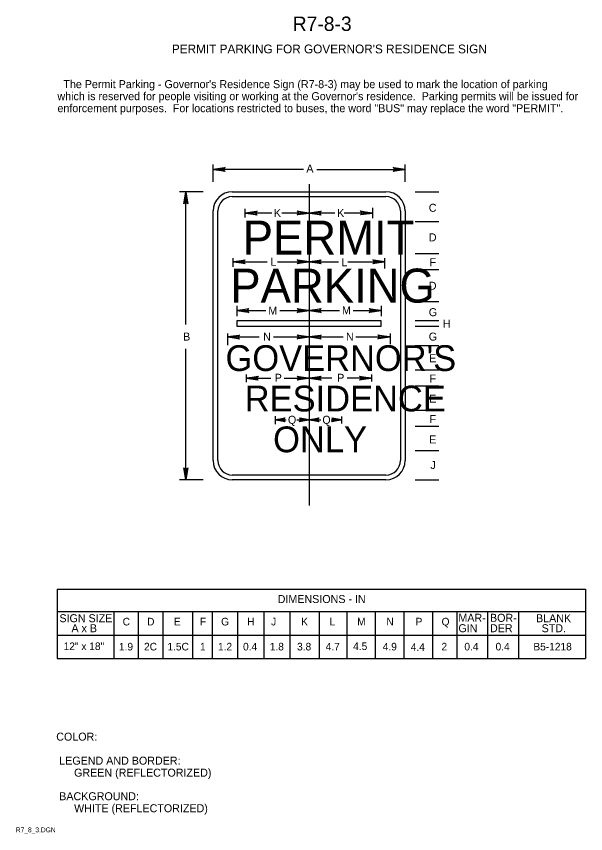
# Model space of a CAD drawing. Extents: x 0.013 to 0.191, y 0.004 to 0.259.
import ezdxf

# ---------------------------------------------------------------- set-up
doc = ezdxf.new("R2010")
doc.units = 0
for name, color, linetype in [('1', 7, 'Continuous'), ('11', 7, 'Continuous'), ('12', 7, 'Continuous'), ('3', 7, 'Continuous')]:
    doc.layers.add(name, color=color, linetype=linetype)

# ---------------------------------------------------------------- blocks, each defined once
blk = doc.blocks.new('RARROW')
at = {"layer": '3'}
for p, q in [((-2.156, 0.285), (-2.2665, 0.384625)), ((-2.2665, 0.384625), (0, 0)), ((0, 0), (-2.2665, -0.379125)), ((-2.156, 0.285), (-2.075625, 0.12075)), ((0, 0), (-2.156, 0.285)), ((-2.14975, -0.2705), (0, 0)), ((-2.075625, 0.12075), (0, 0)), ((0, 0), (-2.074, -0.108)), ((-2.2665, -0.379125), (-2.14975, -0.2705)), ((-2.074, -0.108), (-2.14975, -0.2705))]:
    blk.add_line(p, q, dxfattribs=at)

msp = doc.modelspace()

# ---------------------------------------------------------------- linework, layer by layer
at = {"layer": '11'}
for points in [[(0.08013, 0.2045), (0.12812, 0.2045)], [(0.07412, 0.1205), (0.07412, 0.1985)], [(0.13412, 0.1985), (0.13412, 0.1205)], [(0.12812, 0.1145), (0.08013, 0.1145)]]:
    msp.add_lwpolyline(points, dxfattribs=at)
for centre, start, end in [((0.08013, 0.1985), 90, 180), ((0.12812, 0.1985), 0, 90), ((0.08013, 0.1205), 180, 270), ((0.12812, 0.1205), 270, 0)]:
    msp.add_arc(centre, 0.006, start, end, dxfattribs=at)
at = {"layer": '12'}
for p, q in [((0.08415, 0.19649), (0.08415, 0.19922)), ((0.12388, 0.19948), (0.12388, 0.19628)), ((0.08038, 0.18109), (0.08038, 0.18374)), ((0.12775, 0.18054), (0.12775, 0.18374)), ((0.08149, 0.1689), (0.08149, 0.16562)), ((0.12667, 0.1689), (0.12667, 0.16562)), ((0.07862, 0.16026), (0.07862, 0.15659)), ((0.12947, 0.16025), (0.12947, 0.15692)), ((0.0845, 0.1474), (0.0845, 0.14499)), ((0.12362, 0.1474), (0.12362, 0.14521)), ((0.09349, 0.13436), (0.09349, 0.13184)), ((0.11427, 0.13433), (0.11427, 0.13215))]:
    msp.add_line(p, q, dxfattribs=at)
msp.add_lwpolyline([(0.08154, 0.16248), (0.12667, 0.16248), (0.12667, 0.16418), (0.08154, 0.16418)], close=True, dxfattribs=at)
at = {"layer": '3'}
for p, q in [((0.07412, 0.20763), (0.07412, 0.213)), ((0.13412, 0.20763), (0.13412, 0.213)), ((0.10238, 0.2115), (0.07537, 0.2115)), ((0.1065, 0.2115), (0.13412, 0.2115)), ((0.10412, 0.20688), (0.10412, 0.1065)), ((0.071, 0.2045), (0.06363, 0.2045)), ((0.06563, 0.163), (0.06563, 0.2045)), ((0.13725, 0.2045), (0.14463, 0.2045)), ((0.0925, 0.19787), (0.08413, 0.19787)), ((0.10412, 0.19787), (0.09557, 0.19787)), ((0.11213, 0.19787), (0.10412, 0.19787)), ((0.10413, 0.19871), (0.10413, 0.1971)), ((0.12388, 0.19787), (0.11507, 0.19787)), ((0.13725, 0.19525), (0.14463, 0.19525)), ((0.13725, 0.18525), (0.14463, 0.18525)), ((0.08038, 0.18263), (0.091, 0.18263)), ((0.09422, 0.18263), (0.10412, 0.18263)), ((0.10412, 0.18263), (0.11325, 0.18263)), ((0.1162, 0.18263), (0.12775, 0.18263)), ((0.13725, 0.18025), (0.14463, 0.18025)), ((0.13725, 0.17025), (0.14463, 0.17025)), ((0.0815, 0.16737), (0.09062, 0.16737)), ((0.095, 0.16737), (0.10412, 0.16737)), ((0.10412, 0.16737), (0.11363, 0.16737)), ((0.10413, 0.16834), (0.10413, 0.16673)), ((0.11788, 0.16737), (0.12667, 0.16737)), ((0.13725, 0.16425), (0.14463, 0.16425)), ((0.13725, 0.1625), (0.14463, 0.1625)), ((0.07863, 0.15913), (0.0885, 0.15913)), ((0.09294, 0.15913), (0.10412, 0.15913)), ((0.10412, 0.15913), (0.11475, 0.15913)), ((0.11868, 0.15913), (0.12947, 0.15913)), ((0.13725, 0.1565), (0.14463, 0.1565)), ((0.06563, 0.1145), (0.06563, 0.15545)), ((0.13725, 0.14888), (0.14463, 0.14888)), ((0.0845, 0.14625), (0.09215, 0.14625)), ((0.09632, 0.14625), (0.10407, 0.14625)), ((0.1112, 0.14625), (0.10407, 0.14625)), ((0.12362, 0.14625), (0.11596, 0.14625)), ((0.13725, 0.14388), (0.14463, 0.14388)), ((0.13725, 0.13625), (0.14463, 0.13625)), ((0.0935, 0.13325), (0.097, 0.13325)), ((0.10025, 0.13325), (0.10412, 0.13325)), ((0.10412, 0.13325), (0.10775, 0.13325)), ((0.111, 0.13325), (0.11427, 0.13325)), ((0.13725, 0.13125), (0.14463, 0.13125)), ((0.13725, 0.12362), (0.14463, 0.12362)), ((0.071, 0.1145), (0.06363, 0.1145)), ((0.13725, 0.1145), (0.14463, 0.1145)), ((0.02538, 0.08038), (0.1905, 0.08038)), ((0.02538, 0.08038), (0.02538, 0.05863)), ((0.1905, 0.08038), (0.1905, 0.05863)), ((0.02538, 0.07337), (0.1905, 0.07337)), ((0.04316, 0.07337), (0.04316, 0.05863)), ((0.05074, 0.0735), (0.05074, 0.05863)), ((0.05843, 0.07337), (0.05843, 0.05863)), ((0.06771, 0.0735), (0.06771, 0.05863)), ((0.0738, 0.0735), (0.0738, 0.05863)), ((0.08178, 0.07337), (0.08178, 0.05863)), ((0.08995, 0.07337), (0.08995, 0.05863)), ((0.0981, 0.07337), (0.0981, 0.05863)), ((0.10722, 0.07337), (0.10722, 0.05863)), ((0.11587, 0.07337), (0.11587, 0.05863)), ((0.12479, 0.07337), (0.12479, 0.05863)), ((0.13372, 0.07337), (0.13372, 0.05863)), ((0.14266, 0.0735), (0.14266, 0.05863)), ((0.15025, 0.07337), (0.15025, 0.05863)), ((0.15988, 0.07337), (0.15988, 0.05863)), ((0.1695, 0.07337), (0.1695, 0.05863)), ((0.02538, 0.066), (0.1905, 0.066)), ((0.02538, 0.05863), (0.1905, 0.05863))]:
    msp.add_line(p, q, dxfattribs=at)
for points in [[(0.08013, 0.203), (0.12812, 0.203)], [(0.07562, 0.1205), (0.07562, 0.1985)], [(0.13262, 0.1985), (0.13262, 0.1205)], [(0.12812, 0.116), (0.08013, 0.116)]]:
    msp.add_lwpolyline(points, dxfattribs=at)
for centre, start, end in [((0.08013, 0.1985), 90, 180), ((0.12812, 0.1985), 0, 90), ((0.08013, 0.1205), 180, 270), ((0.12812, 0.1205), 270, 0)]:
    msp.add_arc(centre, 0.0045, start, end, dxfattribs=at)

# ---------------------------------------------------------------- block references
for p, xscale, yscale, rotation in [((0.07412, 0.2115), 0.0016545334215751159, 0.0016366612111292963, 180), ((0.06563, 0.2045), 0.0016545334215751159, 0.0016366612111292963, 90), ((0.08413, 0.19787), 0.0016545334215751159, 0.0016366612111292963, 180), ((0.10412, 0.19787), 0.0016545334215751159, 0.0016366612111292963, 180), ((0.08038, 0.18263), 0.0016545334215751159, 0.0016366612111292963, 180), ((0.10412, 0.18263), 0.0016545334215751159, 0.0016366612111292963, 180), ((0.0815, 0.16737), 0.0016545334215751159, 0.0016366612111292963, 180), ((0.10412, 0.16737), 0.0016545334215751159, 0.0016366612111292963, 180), ((0.07863, 0.15913), 0.0016545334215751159, 0.0016366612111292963, 180), ((0.10412, 0.15913), 0.0016545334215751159, 0.0016366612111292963, 180), ((0.0845, 0.14625), 0.0016545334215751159, 0.0016366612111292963, 180), ((0.10412, 0.14625), 0.0016545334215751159, 0.0016366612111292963, 180), ((0.0935, 0.13325), 0.0013401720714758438, 0.0016366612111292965, 180), ((0.10412, 0.13325), 0.0013401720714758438, 0.0016366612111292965, 180), ((0.06563, 0.1145), 0.0016545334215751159, 0.0016366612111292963, -90)]:
    msp.add_blockref('RARROW', p, dxfattribs=dict(at, xscale=xscale, yscale=yscale, rotation=rotation))
for p, xscale, yscale in [((0.13412, 0.2115), 0.0016545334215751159, 0.0016366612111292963), ((0.10412, 0.19787), 0.0016545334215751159, 0.0016366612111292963), ((0.12387, 0.19787), 0.0016545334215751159, 0.0016366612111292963), ((0.10412, 0.18263), 0.0016545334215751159, 0.0016366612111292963), ((0.12775, 0.18263), 0.0016545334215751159, 0.0016366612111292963), ((0.10412, 0.16737), 0.0016545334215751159, 0.0016366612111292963), ((0.12663, 0.16737), 0.0016545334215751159, 0.0016366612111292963), ((0.10412, 0.15913), 0.0016545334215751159, 0.0016366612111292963), ((0.12937, 0.15913), 0.0016545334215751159, 0.0016366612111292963), ((0.10412, 0.14625), 0.0016545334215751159, 0.0016366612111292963), ((0.12362, 0.14625), 0.0016545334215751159, 0.0016366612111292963), ((0.10412, 0.13325), 0.0013401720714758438, 0.0016366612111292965), ((0.11425, 0.13325), 0.0013401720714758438, 0.0016366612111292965)]:
    msp.add_blockref('RARROW', p, dxfattribs=dict(at, xscale=xscale, yscale=yscale))

# ---------------------------------------------------------------- texts
at = {"layer": '1'}
for s, height, p in [('R7-8-3', 0.0045, (0.099, 0.25475)), ("PERMIT PARKING FOR GOVERNOR'S RESIDENCE SIGN", 0.0027503, (0.06125, 0.24775)), ('COLOR:', 0.0025, (0.02513, 0.033)), (' LEGEND AND BORDER:', 0.0024998, (0.02513, 0.0255)), ('      GREEN (REFLECTORIZED)', 0.0024998, (0.02513, 0.02175)), (' BACKGROUND:', 0.0024998, (0.02513, 0.01438)), ('      WHITE (REFLECTORIZED)', 0.0024998, (0.02513, 0.01063)), ('R7_8_3.DGN', 0.0015, (0.0125, 0.00438))]:
    msp.add_text(s, height=height, dxfattribs=at).set_placement(p)
at = {"layer": '12'}
for s, height, p in [("  The Permit Parking - Governor's Residence Sign (R7-8-3) may be used to mark the location of parking", 0.00249975, (0.0255, 0.23688)), ("which is reserved for people visiting or working at the Governor's residence.  Parking permits will be issued for", 0.00249975, (0.0255, 0.23312)), ('enforcement purposes.  For locations restricted to buses, the word "BUS" may replace the word "PERMIT".', 0.00249975, (0.0255, 0.22937)), ('PERMIT', 0.010617, (0.08338, 0.18488)), ('PARKING', 0.010617, (0.0795, 0.16987)), ("GOVERNOR'S", 0.008053, (0.078, 0.1485)), ('RESIDENCE', 0.008053, (0.084, 0.13587)), ('ONLY', 0.008053, (0.09287, 0.12312))]:
    msp.add_text(s, height=height, dxfattribs=at).set_placement(p)
at = {"layer": '3'}
for s, height, p in [('A', 0.0025, (0.10325, 0.2105)), ('C', 0.0025, (0.1415, 0.19825)), ('K', 0.0025, (0.09312, 0.19662)), ('K', 0.0025, (0.11288, 0.19662)), ('D', 0.0025, (0.1415, 0.189)), ('L', 0.0025, (0.092, 0.18138)), ('L', 0.0025, (0.11425, 0.18125)), ('F', 0.0025, (0.14175, 0.18125)), ('D', 0.0025, (0.1415, 0.17388)), ('M', 0.0025, (0.09137, 0.16612)), ('M', 0.0025, (0.11438, 0.16625)), ('G', 0.0025, (0.1415, 0.16562)), ('H', 0.0025, (0.14588, 0.162)), ('B', 0.0025, (0.06475, 0.158)), ('N', 0.0025, (0.08975, 0.158)), ('N', 0.0025, (0.11563, 0.158)), ('G', 0.0025, (0.1415, 0.158)), ('E', 0.0025, (0.14163, 0.15125)), ('P', 0.0025, (0.09337, 0.14513)), ('P', 0.0025, (0.11288, 0.14513)), ('F', 0.0025, (0.14175, 0.14488)), ('E', 0.0025, (0.14163, 0.13862)), ('Q', 0.0025, (0.0975, 0.132)), ('Q', 0.0025, (0.10825, 0.132)), ('F', 0.0025, (0.14175, 0.13225)), ('E', 0.0025, (0.14163, 0.12588)), ('J', 0.0025, (0.142, 0.11788)), ('DIMENSIONS - IN', 0.0024998, (0.0943, 0.076)), ('SIGN SIZE', 0.0025, (0.02612, 0.07)), ('MAR-', 0.0025, (0.15075, 0.07013)), ('BOR-', 0.0025, (0.16062, 0.07013)), ('BLANK', 0.0025, (0.175, 0.07)), ('A x B', 0.0025, (0.02988, 0.06688)), ('C', 0.00238, (0.04587, 0.069)), ('D', 0.00238, (0.0535, 0.069)), ('E', 0.00238, (0.06187, 0.069)), ('F', 0.00238, (0.07, 0.069)), ('G', 0.00238, (0.07662, 0.069)), ('H', 0.00238, (0.08475, 0.069)), ('J', 0.00238, (0.09225, 0.069)), ('K', 0.00238, (0.10163, 0.069)), ('L', 0.00238, (0.1105, 0.069)), ('M', 0.00238, (0.11913, 0.069)), ('N', 0.00238, (0.12825, 0.069)), ('P', 0.00238, (0.13737, 0.069)), ('Q', 0.00238, (0.1455, 0.069)), ('GIN', 0.0025, (0.15075, 0.06688)), ('DER', 0.0025, (0.16062, 0.06688)), ('STD.', 0.0025, (0.17675, 0.06688)), ('12" x 18"', 0.002375, (0.02743, 0.06131)), ('1.9', 0.002375, (0.04471, 0.06119)), ('2C', 0.002375, (0.05254, 0.06119)), ('1.5C', 0.002375, (0.05985, 0.06119)), ('1', 0.00238, (0.07002, 0.06119)), ('1.2', 0.002375, (0.07564, 0.06119)), ('0.4', 0.002375, (0.08348, 0.06119)), ('1.8', 0.002375, (0.09182, 0.06119)), ('3.8', 0.002375, (0.10036, 0.06119)), ('4.7', 0.002375, (0.10928, 0.06119)), ('4.5', 0.002375, (0.11787, 0.06131)), ('4.9', 0.002375, (0.12712, 0.06119)), ('4.4', 0.002375, (0.13586, 0.06106)), ('2', 0.00238, (0.14545, 0.06119)), ('0.4', 0.002375, (0.15261, 0.06119)), ('0.4', 0.002375, (0.16236, 0.06119)), ('B5-1218', 0.002375, (0.17417, 0.06119))]:
    msp.add_text(s, height=height, dxfattribs=at).set_placement(p)

doc.saveas('drawing.dxf')
